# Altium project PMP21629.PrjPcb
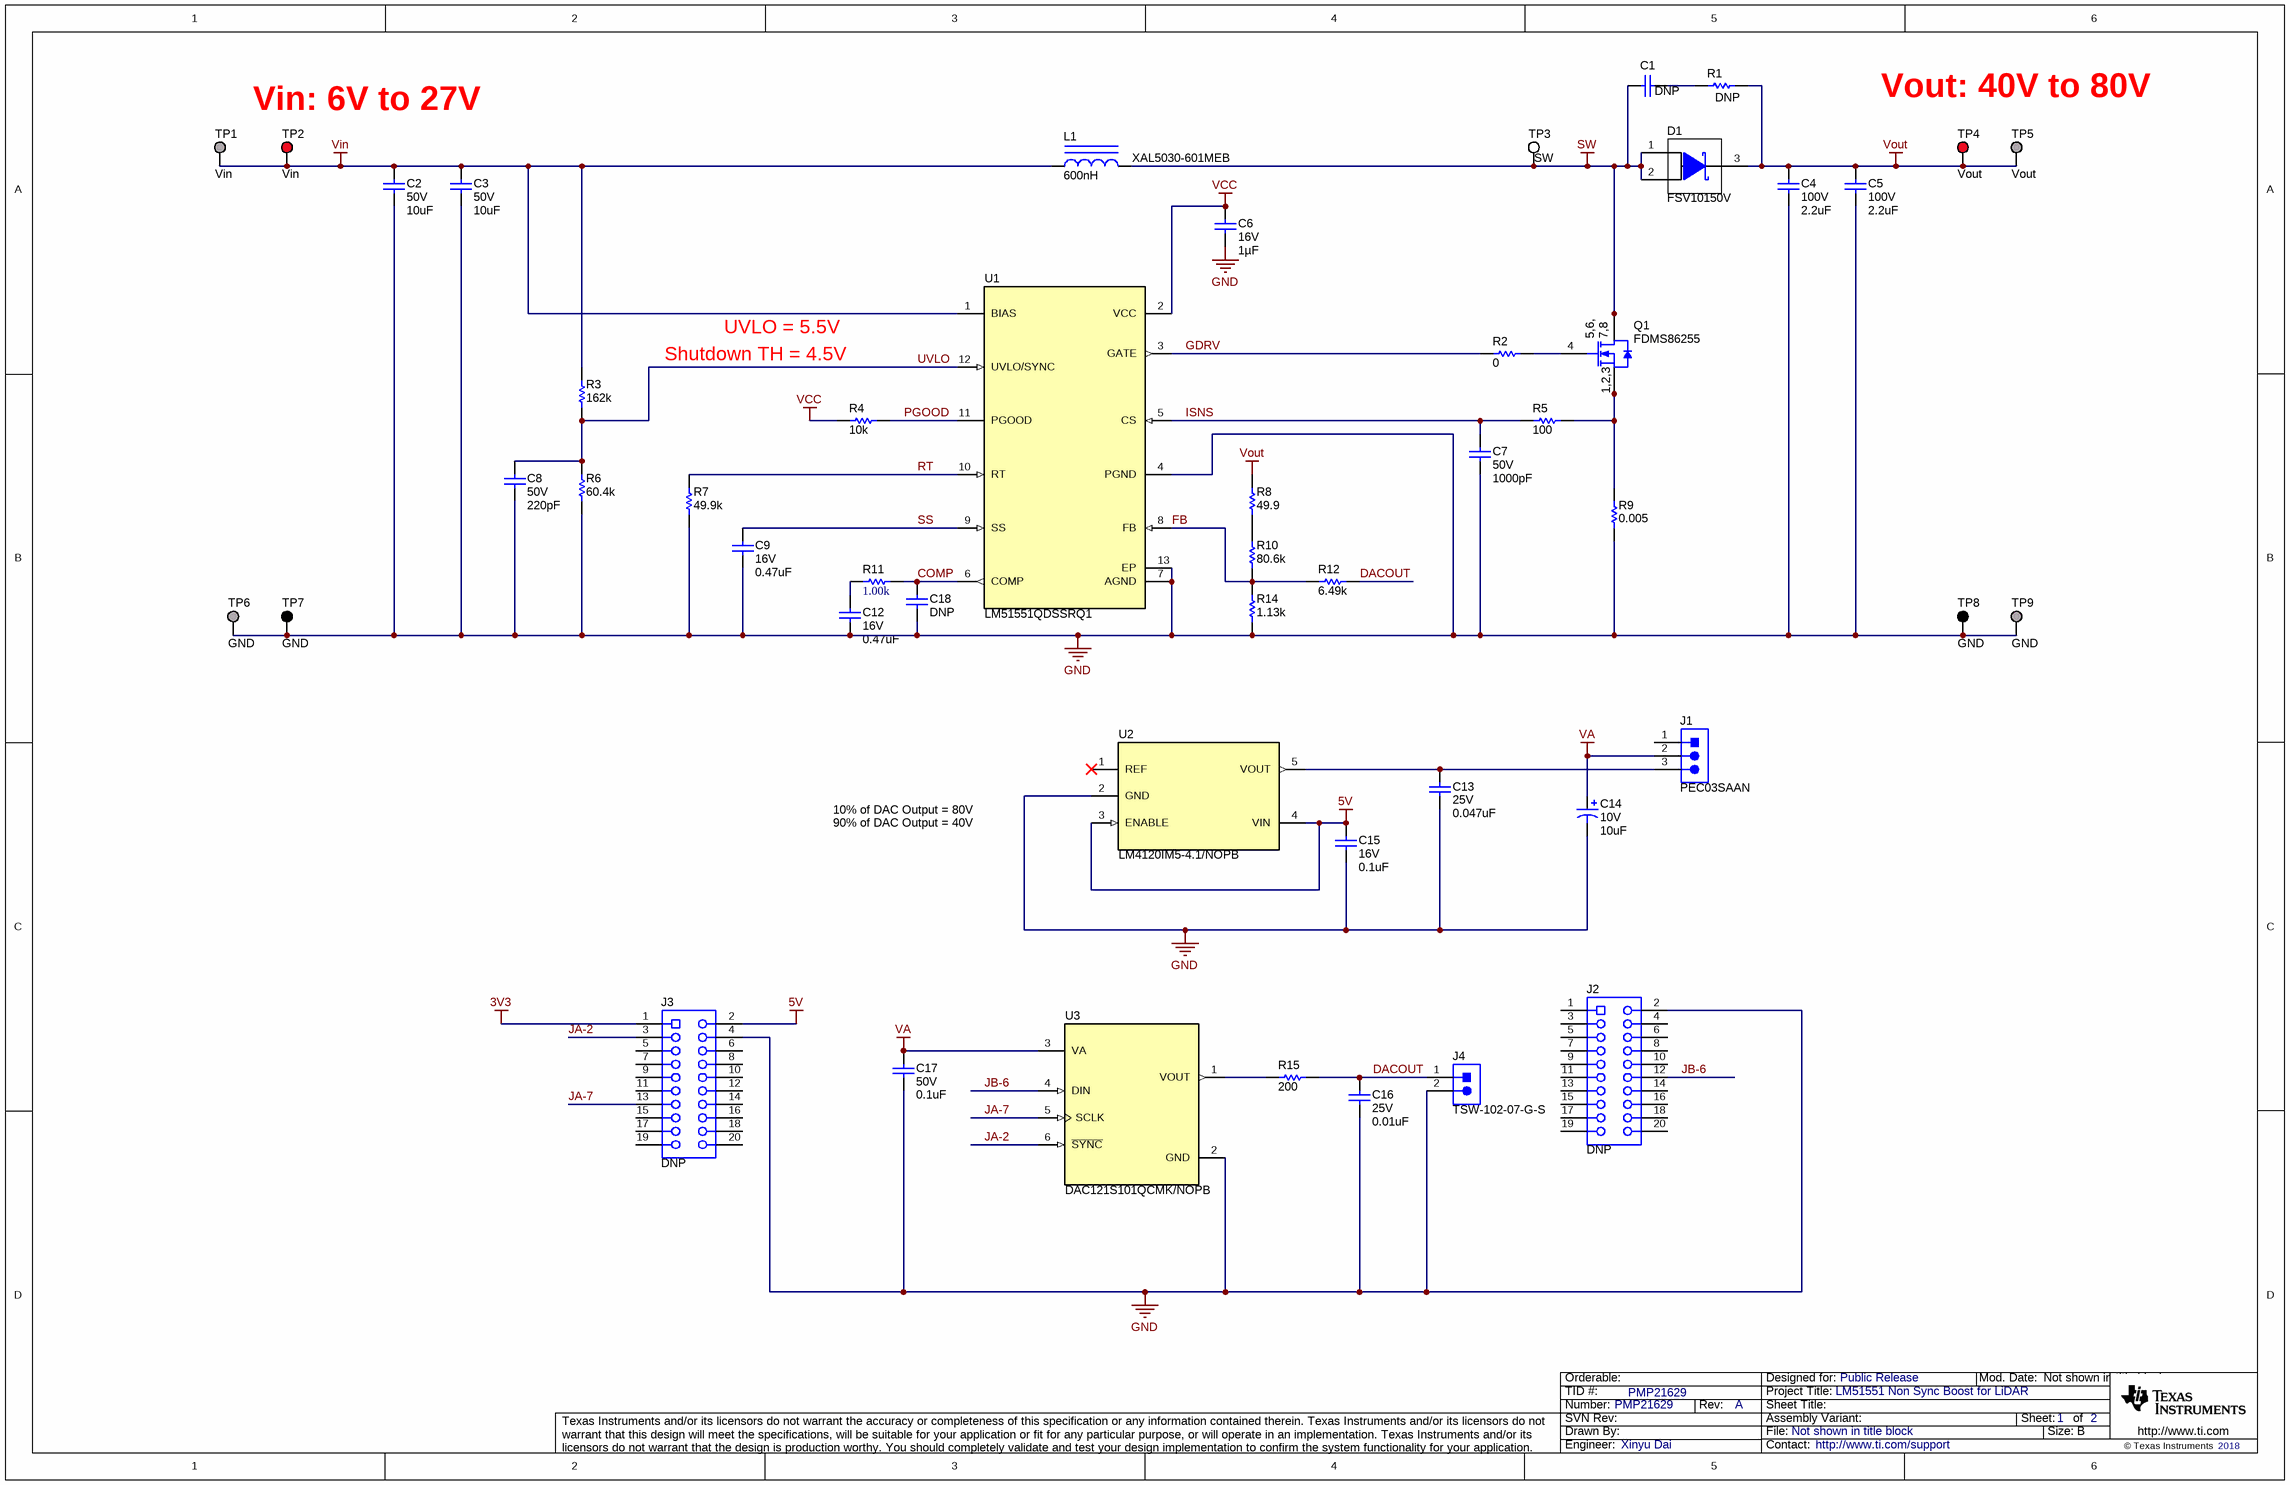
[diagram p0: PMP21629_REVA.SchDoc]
CopyrightYear: 2018; PCB_Layout: Xinyu Dai; PCB_Rev: A; PRJ_Customer: Public Release; PRJ_Engineer: Xinyu Dai; PRJ_Number: PMP21629; PRJ_Title: LM51551 Non Sync Boost for LiDAR; SCH_Rev: A; TechSupport: http://www.ti.com/support; TID: PMP21629
2 sheets, 57 parts. Net scope: global (net labels, ports and power ports of the same name join across sheets).
Board file: PMP21629_REVA.PcbDoc
Sheets:
  PMP21629_REVA.SchDoc
  PMP21629_REVA_Hardware.SchDoc

## Sheet PMP21629_REVA.SchDoc
size 431 x 279 mm; Date: Not shown in title block; ApprovedBy: Not shown in title block; CheckedBy: Not shown in title block; Author: Not shown in title block; CompanyName: Not shown in title block; Engineer: Not shown in title block; Organization: Not shown in title block; Address1: Not shown in title block; Address2: Not shown in title block; Address3: Not shown in title block; Address4: Not shown in title block; DocumentNumber: 1; Revision: Use project parameter SCH_Rev; SheetNumber: 1; SheetTotal: 2; PageSetup: Record=PageOptions¦CenterHorizontal=True¦CenterVertical=True¦PrintScale=1.00¦XCorrection=1.00¦YCorrection=1.00¦PrintKind=0¦BorderSize=5000000¦LeftOffset=0¦BottomOffset=0¦Orientation=2¦PaperLength=1000¦PaperWidth=1000¦Scale=100¦PaperSource=15¦PrintQuality=600¦MediaType=1¦DitherType=10¦PaperKind=Letter¦PrintScaleMode=1

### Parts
C1  DNP  [0805L]
C2  VDC_V: 50V  ValueDisplayed: 10uF  [1210_280]  (hidden comment: C3225X7R1H106M250AC)
C3  VDC_V: 50V  ValueDisplayed: 10uF  [1210_280]  (hidden comment: C3225X7R1H106M250AC)
C4  VDC_V: 100V  ValueDisplayed: 2.2uF  [1210_250L]  (hidden comment: CGA6N3X7R2A225K230AB)
C5  VDC_V: 100V  ValueDisplayed: 2.2uF  [1210_250L]  (hidden comment: CGA6N3X7R2A225K230AB)
C6  VDC_V: 16V  ValueDisplayed: 1µF  [0603L]  (hidden comment: CGA3E1X7R1C105K080AC)
C7  VDC_V: 50V  ValueDisplayed: 1000pF  [0402L]  (hidden comment: GCM155R71H102KA37D)
C8  VDC_V: 50V  ValueDisplayed: 220pF  [0402L]  (hidden comment: GRM1555C1H221JA01D)
C9  VDC_V: 16V  ValueDisplayed: 0.47uF  [0402L]  (hidden comment: GRM155R61C474KE01)
C12  VDC_V: 16V  ValueDisplayed: 0.47uF  [0402L]  (hidden comment: GRM155R61C474KE01)
C13  VDC_V: 25V  ValueDisplayed: 0.047uF  [0402L]  (hidden comment: GRM155R71E473KA88D)
C14  VDC_V: 10V  ValueDisplayed: 10uF  [3216-18]  (hidden comment: TPSA106K010R0900)
C15  VDC_V: 16V  ValueDisplayed: 0.1uF  [0402L]  (hidden comment: C0402C104K4RACAUTO)
C16  VDC_V: 25V  ValueDisplayed: 0.01uF  [0402L]  (hidden comment: GCM155R71E103KA37D)
C17  VDC_V: 50V  ValueDisplayed: 0.1uF  [0402L]  (hidden comment: CGA2B3X7R1H104M050BB)
C18  DNP  [0402L]
D1  FSV10150V  [TO-277A]
J1  PEC03SAAN  [CONN_PEC03SAAN]
J2  DNP  [CONN_SSW-110-23-F-D]
J3  DNP  [CONN_SSW-110-23-F-D]
J4  TSW-102-07-G-S  [TSW-102-07-G-S]
L1  XAL5030-601MEB  ValueDisplayed: 600nH  [XAL5030]
Q1  FDMS86255  [TRANS_NexFET_Q5B]
R1  DNP  [1206L]
R2  ValueDisplayed: 0  [0402L]  (hidden comment: CRCW04020000Z0ED)
R3  ValueDisplayed: 162k  [0402L]  (hidden comment: CRCW0402162KFKED)
R4  ValueDisplayed: 10k  [0402L]  (hidden comment: CRCW040210K0JNED)
R5  ValueDisplayed: 100  [0402L]  (hidden comment: CRCW0402100RJNED)
R6  ValueDisplayed: 60.4k  [0402L]  (hidden comment: CRCW040260K4FKED)
R7  ValueDisplayed: 49.9k  [0402L]  (hidden comment: CRCW040249K9FKED)
R8  ValueDisplayed: 49.9  [1206L]  (hidden comment: RC1206FR-0749R9L)
R9  ValueDisplayed: 0.005  [2512L]  (hidden comment: PMR100HZPFU5L00)
R10  ValueDisplayed: 80.6k  [1206L]  (hidden comment: CRCW120680K6FKEA)
R11  ValueDisplayed: 1.00k  [0402L]  (hidden comment: CRCW04021K00FKED)
R12  ValueDisplayed: 6.49k  [0402L]  (hidden comment: CRCW04026K49FKED)
R14  ValueDisplayed: 1.13k  [0402L]  (hidden comment: CRCW04021K13FKED)
R15  ValueDisplayed: 200  [0402L]  (hidden comment: CRCW0402200RFKED)
TP1  Vin  [Keystone1502-2]
TP2  Vin  [Keystone5000]
TP3  SW  [Keystone5002]
TP4  Vout  [Keystone5000]
TP5  Vout  [Keystone1502-2]
TP6  GND  [Keystone1502-2]
TP7  GND  [Keystone5001]
TP8  GND  [Keystone5001]
TP9  GND  [Keystone1502-2]
U1  LM51551QDSSRQ1  [DSS0012C]
U2  LM4120IM5-4.1/NOPB  [DBV0005A_N]
U3  DAC121S101QCMK/NOPB  [DDC0006A_N]

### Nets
3V3: J3.1
5V: C15.1 J3.2 U2.3(ENABLE) U2.4(VIN)
GND: C2.2 C3.2 C4.2 C5.2 C6.2 C7.2 C8.2 C9.2 C12.2 C13.2 C14.2(-) C15.2 C16.2 C17.1 C18.2 J2.2 J3.4 J4.2 R6.1 R7.1 R9.1 R14.1 TP6.1 TP7.1 TP8.1 TP9.1 U1.4(PGND) U1.7(AGND) U1.13(EP) U2.2(GND) U3.2(GND)
SW: C1.2 D1.1(A) D1.2(A) L1.2 Q1.5(D) Q1.6(D) Q1.7(D) Q1.8(D) TP3.1
VA: C14.1(+) C17.2 J1.2 U3.3(VA)
VCC: C6.1 R4.1 U1.2(VCC)
Vin: C2.1 C3.1 L1.1 R3.2 TP1.1 TP2.1 U1.1(BIAS)
Vout: C4.1 C5.1 D1.3(K) R1.2 R8.2 TP4.1 TP5.1
COMP: C18.1 R11.1 U1.6(COMP)
DACOUT: C16.1 J4.1 R12.2 R15.2
FB: R10.1 R12.1 R14.2 U1.8(FB)
GDRV: R2.1 U1.3(GATE)
ISNS: C7.1 R5.1 U1.5(CS)
JA-2: J3.3 U3.6(~{SYNC})
JA-7: J3.13 U3.5(SCLK)
JB-6: J2.12 U3.4(DIN)
PGOOD: R4.2 U1.11(PGOOD)
RT: R7.2 U1.10(RT)
SS: C9.1 U1.9(SS)
UVLO: C8.1 R3.1 R6.2 U1.12(UVLO/SYNC)
NetC1_1: C1.1 R1.1
NetC12_1: C12.1 R11.2
NetC13_1: C13.1 J1.3 U2.5(VOUT)
NetQ1_1: Q1.1(S) Q1.2(S) Q1.3(S) R5.2 R9.2
NetQ1_4: Q1.4(G) R2.2
NetR8_1: R8.1 R10.2
NetR15_1: R15.1 U3.1(VOUT)

Not connected (* = marked no-connect by the designer): J1 1; J2 1 3 4 5 6 7 8 9 10 11 13 14 15 16 17 18 19 20; J3 5 6 7 8 9 10 11 12 14 15 16 17 18 19 20; U2 1(REF)*

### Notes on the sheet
- Vin: 6V to 27V
- Vout: 40V to 80V
- Shutdown TH = 4.5V
- UVLO = 5.5V
- 10% of DAC Output = 80V
- 90% of DAC Output = 40V

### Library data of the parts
C1 = CMP-0008122-2: CAP, CERM, 470 pF, 100 V, +/- 5%, C0G/NP0, 0805; Manufacturer: MuRata; PartNumber: GRM2165C2A471JA01D; TaMin_C: -55°C; Polarized: N; SizeAreaWB_mm2: 6.75; Value1: Unknown; U/M: EA; Value: 470pF; TaMax_C: 125°C; SizeZ_mm: 1.45; SizeX_mm: 2; SizeY_mm: 1.25; Cap_Case: 0805; Value2: 100V; SizeArea_mm2: 2.5; CompType: Capacitor; AEC Category: Q200
C2 C3 = CMP-0009120-1: CAP, CERM, 10 uF, 50 V, +/- 20%, X7R, 1210; Manufacturer: TDK; TaMin_C: -55°C; Polarized: N; SizeAreaWB_mm2: 14.7; Value1: Unknown; U/M: EA; Value: 10uF; TaMax_C: 125°C; SizeZ_mm: 2.8; SizeX_mm: 3.2; SizeY_mm: 2.5; Cap_Case: 1210; SizeArea_mm2: 8; CompType: Capacitor; Cap_F: 10µF; AEC Category: Q200
C4 C5 = CMP-0009152-2: CAP, CERM, 2.2 uF, 100 V, +/- 10%, X7R, AEC-Q200 Grade 1,; Manufacturer: TDK; TaMin_C: -55°C; ESR_ohm: 1.73m; Polarized: N; SizeAreaWB_mm2: 14.7; Value1: 0.00173 ohm; U/M: EA; Value: 2.2uF; TaMax_C: 125°C; SizeZ_mm: 2.5; SizeX_mm: 3.2; Cap_Case: 1210_250; SizeArea_mm2: 8; CompType: Capacitor; AEC Qualified: Y; Cap_F: 2.2µF; IRMS_A: 5.59317A; AEC Grade: 1; AEC Category: Q200
C6 = CMP-0079607-1: CAP, CERM, 1 µF, 16 V,+/- 10%, X7R, AEC-Q200 Grade 1, 0603; Manufacturer: TDK; TaMin_C: -55°C; Polarized: N; SizeAreaWB_mm2: 4.68; U/M: EA; Value: 1uF; TaMax_C: 125°C; SizeZ_mm: 1; SizeX_mm: 1.6; SizeY_mm: 0.8; Cap_Case: 0603; SizeArea_mm2: 1.28; CompType: Capacitor; AEC Qualified: Y; AEC Category: Q200
C7 = CMP-0006354-2: CAP, CERM, 1000 pF, 50 V, +/- 10%, X7R, AEC-Q200 Grade 1, 0402; Manufacturer: MuRata; TaMin_C: -55°C; Polarized: N; SizeAreaWB_mm2: 3; Value1: Unknown; U/M: EA; Value: 1000pF; TaMax_C: 125°C; SizeZ_mm: 0.6; SizeX_mm: 1; SizeY_mm: 0.5; Cap_Case: 0402; CompType: Capacitor; AEC Qualified: Y; Cap_F: 1nF; AEC Category: Q200
C8 = CMP-0006440-2: CAP, CERM, 220 pF, 50 V, +/- 5%, C0G/NP0, 0402; Manufacturer: MuRata; TaMin_C: -55°C; Polarized: N; SizeAreaWB_mm2: 3; Value1: Unknown; U/M: EA; Value: 220pF; TaMax_C: 125°C; SizeZ_mm: 0.6; SizeX_mm: 1; SizeY_mm: 0.5; Cap_Case: 0402; CompType: Capacitor; AEC Category: Q200
C9 C12 = CMP-0006600-2: CAP, CERM, 0.47 uF, 16 V, +/- 10%, X5R, 0402; Manufacturer: MuRata; TaMin_C: -55°C; Polarized: N; SizeAreaWB_mm2: 3; Value1: Unknown; U/M: EA; Value: 0.47uF; TaMax_C: 85°C; SizeZ_mm: 0.6; SizeX_mm: 1; SizeY_mm: 0.5; Cap_Case: 0402; CompType: Capacitor; Cap_F: 470nF; AEC Category: Q200
C13 = CMP-0006669-2: CAP, CERM, 0.047 uF, 25 V, +/- 10%, X7R, 0402; Manufacturer: MuRata; TaMin_C: -55°C; Polarized: N; SizeAreaWB_mm2: 3; Value1: Unknown; U/M: EA; TaMax_C: 125°C; SizeZ_mm: 0.6; SizeX_mm: 1; SizeY_mm: 0.5; Cap_Case: 0402; CompType: Capacitor; Cap_F: 47nF; AEC Category: Q200
C14 = CMP-0011484-2: CAP, TA, 10 uF, 10 V, +/- 10%, 0.9 ohm, SMD; Manufacturer: AVX; TaMin_C: -55°C; ESR_ohm: 9d; Polarized: Y; SizeAreaWB_mm2: 10.92; Value1: 0.9 ohm; U/M: EA; Value: 10uF; TaMax_C: 125°C; SizeZ_mm: 1.8; SizeX_mm: 3.2; SizeY_mm: 1.6; Cap_Case: A; SizeArea_mm2: 5.12; CompType: Capacitor; Cap_F: 10µF; IRMS_A: 2.6dA; AEC Category: Q200
C15 = CMP-0006237-2: CAP, CERM, 0.1 uF, 16 V, +/- 10%, X7R, AEC-Q200 Grade 1, 0402; Manufacturer: Kemet; TaMin_C: -55°C; Polarized: N; SizeAreaWB_mm2: 3; Value1: Unknown; U/M: EA; Value: 0.1uF; TaMax_C: 125°C; SizeZ_mm: 0.6; SizeX_mm: 1; SizeY_mm: 0.5; Cap_Case: 0402; CompType: Capacitor; AEC Qualified: Y; Cap_F: 100nF; AEC Category: Q200
C16 = CMP-0006352-2: CAP, CERM, 0.01 uF, 25 V, +/- 10%, X7R, 0402; Manufacturer: MuRata; TaMin_C: -55°C; Polarized: N; SizeAreaWB_mm2: 3; Value1: Unknown; U/M: EA; Value: 0.01uF; TaMax_C: 125°C; SizeZ_mm: 0.6; SizeX_mm: 1; SizeY_mm: 0.5; Cap_Case: 0402; CompType: Capacitor; Cap_F: 10nF; AEC Category: Q200
C17 = CMP-0006326-2: CAP, CERM, 0.1 uF, 50 V, +/- 20%, X7R, AEC-Q200 Grade 1, 0402; Manufacturer: TDK; TaMin_C: -55°C; Polarized: N; SizeAreaWB_mm2: 3; Value1: Unknown; U/M: EA; Value: 0.1uF; TaMax_C: 125°C; SizeZ_mm: 0.6; SizeX_mm: 1; SizeY_mm: 0.5; Cap_Case: 0402; CompType: Capacitor; AEC Qualified: Y; Cap_F: 100nF; AEC Category: Q200
C18 = CMP-0006354-2: CAP, CERM, 1000 pF, 50 V, +/- 10%, X7R, AEC-Q200 Grade 1, 0402; Manufacturer: MuRata; PartNumber: GCM155R71H102KA37D; TaMin_C: -55°C; Polarized: N; SizeAreaWB_mm2: 3; Value1: Unknown; U/M: EA; Value: 1000pF; TaMax_C: 125°C; SizeZ_mm: 0.6; SizeX_mm: 1; SizeY_mm: 0.5; Cap_Case: 0402; Value2: 50V; CompType: Capacitor; AEC Qualified: Y; Cap_F: 1nF; AEC Category: Q200
D1 = CMP-0028890-1: Diode, Schottky, 150 V, 10 A, AEC-Q101, TO-277A; Manufacturer: Fairchild Semiconductor; Io_A: 10A; Green_Lifecycle: Not Set; SizeAreaWB_mm2: 57.375; Vr_V: 150V; Green_REACh: Incomplete; TJmax_C: 150°C; U/M: EA; Value: 150V; SizeZ_mm: 1.2; SizeX_mm: 6.5; SizeY_mm: 4.75; Vf_V: 8.4dV; Value2: 0.84V; SizeArea_mm2: 30.875; AEC Qualified: Y; AEC Category: Q101
J1 = CMP-0002338-1: Header, 100mil, 3x1, Tin, TH; Manufacturer: Sullins Connector Solutions; CNHeader: TRUE; Current_A: 3A; Green_Lifecycle: Not Set; Shrouded: N; Gender: Male; Green_REACh: Incomplete; Voltage_V: 1.8kV; Row_Count: 1; Pitch_mm: 2.54; CT: FALSE; Cert_UL: Y
J2 J3 = CMP-0075442-1: Connector, Receptacle, 100mil, 10x2, Gold plated, TH; PartNumber: SSW-110-23-F-D; Manufacturer: Samtec; Green_Lifecycle: Active; CompType: Socket Strip; Green_REACh: Passed; CT: True; CNHeader: False
J4 = CMP-0075405-2: Header, 100mil, 2x1, Gold, TH; Manufacturer: Samtec; Pitch_mm: 2.54; Cert_VDE: N; Gender: Male; Cert_CSA: Y; Voltage_V: 550V; Green_REACh: Passed; Current_A: 6.3A; Green_Lifecycle: Active; Row_Count: 1
L1 = CMP-0061005-2: Inductor, Shielded, Composite, 600 nH, 17.7 A, 0.00411 ohm, AEC-Q200 Grade 1, SMD; Manufacturer: Coilcraft; Isat: 19.8A @ 30% inductance drop; Irms: 17.7A @ 40C rise; Green_Lifecycle: Not Set; SizeAreaWB_mm2: 54.4544; DCR_ohm: 4.11m; Green_REACh: Incomplete; Value: 600nH; Imax_A: 17.7A; SizeZ_mm: 3.1; SizeX_mm: 5.28; SizeY_mm: 5.48; SizeArea_mm2: 28.9344; AEC Qualified: 1; AEC Category: Q200; AEC Grade: Y
Q1 = CMP-0001059-1: MOSFET, N-CH, 150 V, 10 A, SON 5x6mm; Alternate Manufacturer: None; Manufacturer: Fairchild Semiconductor; SizeZ_mm: 1.05; ChType: N; Value2: 45 nC; VdsMax_V: 150V; SizeX_mm: 6.1; SizeY_mm: 5.1; Vgs_V: 20V; QgTyp_nC: 45; Value: 150V; SizeArea_mm2: 31.11; AEC Category: Q101; IdsMax_A: 10A; SizeAreaWB_mm2: 57.51; U/M: EA
R1 = CMP-0017049-3: RES, 4.99, 1%, 0.25 W, AEC-Q200 Grade 0, 1206; Manufacturer: Vishay-Dale; PartNumber: CRCW12064R99FKEA; Power_W: 250mW; TempCo: 100 ppm/C; Value_Code: 4R99; Value: 4.99; EIA_Code: E96; SizeX_mm: 3.2; SizeY_mm: 1.6; SizeZ_mm: 1.35; Value2: 0.25W; SizeArea_mm2: 5.12; CompType: Resistor; AEC Qualified: Y; VDC_V: 200V; AEC Category: Q200; AEC Grade: 0
R2 = CMP-0026822-3: RES, 0, 5%, 0.063 W, AEC-Q200 Grade 0, 0402; Manufacturer: Vishay-Dale; Power_W: 63mW; TempCo: 200 ppm/C; Value_Code: 0000; Value: 0; EIA_Code: E24; SizeX_mm: 1; SizeY_mm: 0.5; SizeZ_mm: 0.6; Value2: 0.063W; AEC Qualified: Y; VDC_V: 50V; AEC Category: Q200
R3 = CMP-0026034-3: RES, 162 k, 1%, 0.063 W, AEC-Q200 Grade 0, 0402; Manufacturer: Vishay-Dale; Power_W: 63mW; TempCo: 100 ppm/C; Value: 162k; EIA_Code: E96; SizeX_mm: 1; SizeY_mm: 0.5; SizeZ_mm: 0.6; Value2: 0.063W; CompType: Resistor; AEC Qualified: Y; VDC_V: 50V; AEC Category: Q200; AEC Grade: 0
R4 = CMP-0026825-5: RES, 10 k, 5%, 0.063 W, AEC-Q200 Grade 0, 0402; Manufacturer: Vishay-Dale; Power_W: 63mW; TempCo: 200 ppm/C; Value_Code: 10k0; Value: 10k; EIA_Code: E24; SizeX_mm: 1; SizeY_mm: 0.5; SizeZ_mm: 0.6; Value2: 0.063W; CompType: Resistor; AEC Qualified: Y; VDC_V: 50V; AEC Category: Q200; AEC Grade: 0
R5 = CMP-0026824-3: RES, 100, 5%, 0.063 W, AEC-Q200 Grade 0, 0402; Manufacturer: Vishay-Dale; Power_W: 63mW; TempCo: 200 ppm/C; Value_Code: 100R; Value: 100; EIA_Code: E24; SizeX_mm: 1; SizeY_mm: 0.5; SizeZ_mm: 0.6; Value2: 0.063W; CompType: Resistor; AEC Qualified: Y; VDC_V: 50V; AEC Category: Q200; AEC Grade: 0
R6 = CMP-0026486-2: RES, 60.4 k, 1%, 0.063 W, AEC-Q200 Grade 0, 0402; Manufacturer: Vishay-Dale; Power_W: 63mW; TempCo: 100 ppm/C; Value_Code: 60k4; Value: 60.4k; EIA_Code: E96; SizeX_mm: 1; SizeY_mm: 0.5; SizeZ_mm: 0.6; Value2: 0.063W; CompType: Resistor; AEC Qualified: Y; VDC_V: 50V; AEC Category: Q200; AEC Grade: 0
R7 = CMP-0026403-2: RES, 49.9 k, 1%, 0.063 W, AEC-Q200 Grade 0, 0402; Manufacturer: Vishay-Dale; Power_W: 63mW; TempCo: 100 ppm/C; Value_Code: 49k9; Value: 49.9k; EIA_Code: E96; SizeX_mm: 1; SizeY_mm: 0.5; SizeZ_mm: 0.6; Value2: 0.063W; CompType: Resistor; AEC Qualified: Y; VDC_V: 50V; AEC Category: Q200; AEC Grade: 0
R8 = CMP-0018328-2: RES, 49.9, 1%, 0.25 W, 1206; Manufacturer: Yageo America; Power_W: 250mW; TempCo: 100 ppm/C; Value_Code: 49R9; U/M: EA; Value: 49.9; EIA_Code: E96; SizeX_mm: 3.2; SizeY_mm: 1.6; SizeZ_mm: 1.35; Value2: 0.25W; SizeArea_mm2: 5.12; CompType: Resistor; VDC_V: 200V; AEC Category: Q200
R9 = CMP-0015837-2: RES, 0.005, 1%, 2 W, 2512; Manufacturer: Rohm; Power_W: 2W; TempCo: 100 ppm/C; Value_Code: 5L000; U/M: EA; Value: 0.005; EIA_Code: E96; Res_ohm: 5m; SizeX_mm: 6.3; SizeY_mm: 3.2; SizeZ_mm: 0.71; SizeArea_mm2: 20.16; CompType: Resistor; AEC Category: Q200
R10 = CMP-0017185-3: RES, 80.6 k, 1%, 0.25 W, AEC-Q200 Grade 0, 1206; Manufacturer: Vishay-Dale; Power_W: 250mW; TempCo: 100 ppm/C; Value_Code: 80k6; Value: 80.6k; EIA_Code: E96; SizeX_mm: 3.2; SizeY_mm: 1.6; SizeZ_mm: 1.35; Value2: 0.25W; SizeArea_mm2: 5.12; CompType: Resistor; AEC Qualified: Y; VDC_V: 200V; AEC Category: Q200; AEC Grade: 0
R11 = CMP-0026071-3: RES, 1.00 k, 1%, 0.063 W, AEC-Q200 Grade 0, 0402; Manufacturer: Vishay-Dale; Power_W: 63mW; TempCo: 100 ppm/C; Value_Code: 1k00; Value: 1.00k; EIA_Code: E96; Res_ohm: 1k; SizeX_mm: 1; SizeY_mm: 0.5; SizeZ_mm: 0.6; Value2: 0.063W; AEC Qualified: Y; VDC_V: 50V; AEC Category: Q200; AEC Grade: 0
R12 = CMP-0026515-2: RES, 6.49 k, 1%, 0.063 W, AEC-Q200 Grade 0, 0402; Manufacturer: Vishay-Dale; Power_W: 63mW; TempCo: 100 ppm/C; Value_Code: 6k49; Value: 6.49k; EIA_Code: E96; SizeX_mm: 1; SizeY_mm: 0.5; SizeZ_mm: 0.6; Value2: 0.063W; CompType: Resistor; AEC Qualified: Y; VDC_V: 50V; AEC Category: Q200; AEC Grade: 0
R14 = CMP-0026076-3: RES, 1.13 k, 1%, 0.063 W, AEC-Q200 Grade 0, 0402; Manufacturer: Vishay-Dale; Power_W: 63mW; TempCo: 100 ppm/C; Value_Code: 1k13; Value: 1.13k; EIA_Code: E96; SizeX_mm: 1; SizeY_mm: 0.5; SizeZ_mm: 0.6; Value2: 0.063W; CompType: Resistor; AEC Qualified: Y; VDC_V: 50V; AEC Category: Q200; AEC Grade: 0
R15 = CMP-0026159-2: RES, 200, 1%, 0.063 W, AEC-Q200 Grade 0, 0402; Manufacturer: Vishay-Dale; Power_W: 63mW; TempCo: 100 ppm/C; Value_Code: 200R; Value: 200; EIA_Code: E96; SizeX_mm: 1; SizeY_mm: 0.5; SizeZ_mm: 0.6; Value2: 0.063W; CompType: Resistor; AEC Qualified: Y; VDC_V: 50V; AEC Category: Q200; AEC Grade: 0
TP1 TP5 TP6 TP9 = CMP-0055113-1: Terminal, Turret, TH, Double; Manufacturer: Keystone; PartNumber: 1502-2; CT: FALSE; Green_REACh: Passed; CompType: Turret Terminal; Green_Lifecycle: Active
TP2 TP4 = CMP-0055137-1: Test Point, Miniature, Red, TH; Manufacturer: Keystone; PartNumber: 5000; CNHeader: FALSE; Green_Lifecycle: Active; Green_REACh: Passed; ContactFinish: Silver; CT: TRUE
TP3 = CMP-0055139-1: Test Point, Miniature, White, TH; Manufacturer: Keystone; PartNumber: 5002; CNHeader: FALSE; Green_Lifecycle: Active; Green_REACh: Passed; ContactFinish: Silver; CT: TRUE
TP7 TP8 = CMP-0055138-1: Test Point, Miniature, Black, TH; Manufacturer: Keystone; PartNumber: 5001; CNHeader: FALSE; Green_Lifecycle: Active; Green_REACh: Passed; ContactFinish: Silver; CT: TRUE
U1 = CMP-0081541-1: Automotive Grade 2.2-MHz Wide Input Non-synchronous Boost Controller, DSS0012C (WSON-12); Alternate PartNumber: LM51551QDSSTQ1; Alternate Manufacturer: Texas Instruments; SizeAreaWB_mm2: 12; SizeZ_mm: 0.8; SizeX_mm: 2; SizeY_mm: 3; SizeArea_mm2: 6; CompType: IC; AEC Qualified: Y; AEC Category: Q200
U2 = CMP-0079364-1: 0.2% 50ppm/°C Drift Precision Series Voltage Reference with Shutdown Enable, DBV0005A (SOT-23-5); Alternate PartNumber: LM4120IM5X-4.1/NOPB; Alternate Manufacturer: Texas Instruments; Green_Lifecycle: Active; SizeAreaWB_mm2: 14.82; Green_REACh: Passed; SizeZ_mm: 1.45; SizeX_mm: 2.8; SizeY_mm: 2.9; SizeArea_mm2: 8.12; CompType: IC; AEC Qualified: N; AEC Category: Q200
U3 = CMP-0083725-1: 12-Bit Micro Power, RRO Digital-to-Analog Converter, DDC0006A (SOT-23-THIN-6); Alternate PartNumber: DAC121S101QCMKX/NOPB; Alternate Manufacturer: Texas Instruments; SizeAreaWB_mm2: 10.4675; Rating: Automotive; SizeZ_mm: 0.87; SizeX_mm: 1.65; SizeY_mm: 2.95; SizeArea_mm2: 4.8675; CompType: IC; AEC Qualified: Y; AEC Category: Q200

## Sheet PMP21629_REVA_Hardware.SchDoc
size 431 x 279 mm; Date: Not shown in title block; ApprovedBy: Not shown in title block; CheckedBy: Not shown in title block; Author: Not shown in title block; CompanyName: Not shown in title block; Engineer: Not shown in title block; Organization: Not shown in title block; Address1: Not shown in title block; Address2: Not shown in title block; Address3: Not shown in title block; Address4: Not shown in title block; DocumentNumber: 1; Revision: Use project parameter SCH_Rev; SheetNumber: 2; SheetTotal: 2; PageSetup: Record=PageOptions¦CenterHorizontal=True¦CenterVertical=True¦PrintScale=1.00¦XCorrection=1.00¦YCorrection=1.00¦PrintKind=0¦BorderSize=5000000¦LeftOffset=0¦BottomOffset=0¦Orientation=2¦PaperLength=1000¦PaperWidth=1000¦Scale=100¦PaperSource=15¦PrintQuality=600¦MediaType=1¦DitherType=10¦PaperKind=Letter¦PrintScaleMode=1
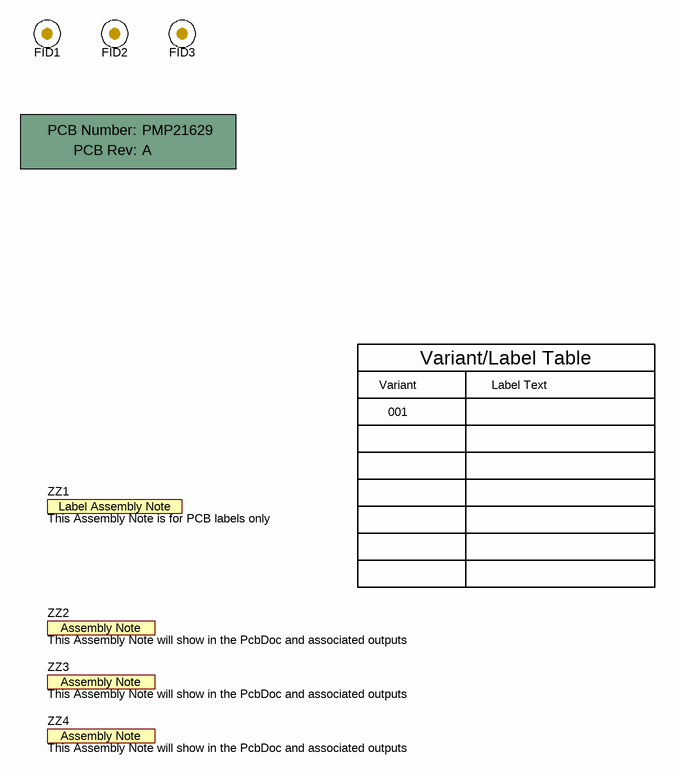
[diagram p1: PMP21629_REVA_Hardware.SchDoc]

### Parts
!PCB1  Printed Circuit Board  (value not drawn)  (mechanical)
FID1  Fiducial  [Fiducial10-20]  (value not drawn)
FID2  Fiducial  [Fiducial10-20]  (value not drawn)
FID3  Fiducial  [Fiducial10-20]  (value not drawn)
ZZ1  This Assembly Note is for PCB labels only  [AssemblyNoteLabel]  (no BOM)
ZZ2  This Assembly Note will show in the PcbDoc and associated outputs  [AssemblyNote]  (no BOM)
ZZ3  This Assembly Note will show in the PcbDoc and associated outputs  [AssemblyNote]  (no BOM)
ZZ4  This Assembly Note will show in the PcbDoc and associated outputs  [AssemblyNote]  (no BOM)

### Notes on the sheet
- Variant
- Variant/Label Table
- Label Text
- 001

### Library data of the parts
!PCB1 = PCB: Manufacturer: Any; PartNumber: PMP21629; SymbolCreator: a0412235
FID1-FID3 = Fiducial: Fiducial mark.  There is nothing to buy or mount.; SymbolCreator: codlsc
ZZ1 = AssemblyNoteLabel: SymbolCreator: a0412235
ZZ2-ZZ4 = AssemblyNote: SymbolCreator: codlsc

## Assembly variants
001: not fitted C1 C18 FID1 FID2 FID3 R1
